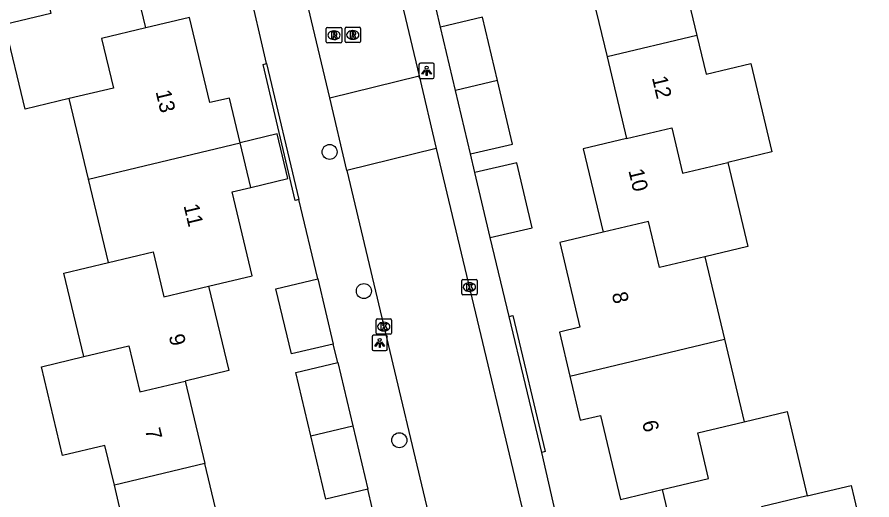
# Model space of a CAD drawing. Extents: x 158038 to 159242, y 380133 to 381214.
# Drawn here: x 158907 to 158962.6, y 380506.3 to 380537.7 of the extents above; entities that cross this region are included whole.
import ezdxf

# ---------------------------------------------------------------- set-up
doc = ezdxf.new("R2010")
doc.units = 0
for name, color, linetype in [('IMGEO_Boom', 7, 'Continuous'), ('IMGEO_Kolk', 7, 'Continuous'), ('IMGEO_Lichtpunt', 7, 'Continuous'), ('IMGEO_Muur', 7, 'Continuous'), ('IMGEO_Pand', 7, 'Continuous'), ('IMGEO_Pand_nummerreeks', 7, 'Continuous'), ('IMGEO_Rijbaan_lokaal_open', 7, 'Continuous'), ('IMGEO_Rioolput', 7, 'Continuous'), ('IMGEO_Voetpad_open', 7, 'Continuous')]:
    doc.layers.add(name, color=color, linetype=linetype)

msp = doc.modelspace()

# ---------------------------------------------------------------- linework, layer by layer
at = {"layer": 'IMGEO_Boom'}
for centre in [(158927.327, 380528.904), (158929.556, 380519.852), (158931.862, 380510.146)]:
    msp.add_circle(centre, 0.489, dxfattribs=at)
at = {"layer": 'IMGEO_Kolk'}
for p, q in [((158936.001, 380520.611), (158936.853, 380520.611)), ((158935.926, 380519.685), (158935.926, 380520.537)), ((158936.414, 380520.391), (158936.439, 380520.391)), ((158936.927, 380520.537), (158936.927, 380519.685)), ((158936.853, 380519.611), (158936.001, 380519.611)), ((158936.437, 380519.831), (158936.412, 380519.831)), ((158930.351, 380517.112), (158930.351, 380517.964)), ((158930.426, 380518.038), (158931.278, 380518.038)), ((158930.839, 380517.818), (158930.864, 380517.818)), ((158931.352, 380517.964), (158931.352, 380517.112)), ((158930.862, 380517.258), (158930.837, 380517.258)), ((158931.278, 380517.038), (158930.426, 380517.038))]:
    msp.add_line(p, q, dxfattribs=at)
for points in [[(158936.001, 380520.611), (158936.853, 380520.611)], [(158935.926, 380519.685), (158935.926, 380520.537)], [(158936.247, 380520.311), (158936.37, 380520.311), (158936.37, 380520.16), (158936.5, 380520.311), (158936.664, 380520.311), (158936.518, 380520.16), (158936.671, 380519.911), (158936.519, 380519.911), (158936.434, 380520.075), (158936.37, 380520.008), (158936.37, 380519.911), (158936.247, 380519.911), (158936.247, 380520.311)], [(158936.927, 380520.537), (158936.927, 380519.685)], [(158936.853, 380519.611), (158936.001, 380519.611)], [(158930.351, 380517.112), (158930.351, 380517.964)], [(158930.426, 380518.038), (158931.278, 380518.038)], [(158931.352, 380517.964), (158931.352, 380517.112)], [(158930.672, 380517.738), (158930.795, 380517.738), (158930.795, 380517.587), (158930.925, 380517.738), (158931.089, 380517.738), (158930.943, 380517.587), (158931.096, 380517.338), (158930.944, 380517.338), (158930.859, 380517.502), (158930.795, 380517.435), (158930.795, 380517.338), (158930.672, 380517.338), (158930.672, 380517.738)], [(158931.278, 380517.038), (158930.426, 380517.038)]]:
    msp.add_lwpolyline(points, dxfattribs=at)
for centre, start, end in [((158936.003, 380520.535), 91.552, 178.448), ((158936.003, 380520.535), 91.552, 178.448), ((158936.851, 380520.535), 1.552, 88.448), ((158936.851, 380520.535), 1.552, 88.448), ((158936.003, 380519.687), 181.552, 268.448), ((158936.003, 380519.687), 181.552, 268.448), ((158936.851, 380519.687), 271.552, 358.448), ((158936.851, 380519.687), 271.552, 358.448), ((158930.428, 380517.962), 91.552, 178.448), ((158930.428, 380517.962), 91.552, 178.448), ((158931.276, 380517.962), 1.552, 88.448), ((158931.276, 380517.962), 1.552, 88.448), ((158930.428, 380517.114), 181.552, 268.448), ((158930.428, 380517.114), 181.552, 268.448), ((158931.276, 380517.114), 271.552, 358.448), ((158931.276, 380517.114), 271.552, 358.448)]:
    msp.add_arc(centre, 0.0765, start, end, dxfattribs=at)
for centre, major_axis, ratio, start_param, end_param in [((158936.413, 380520.111), (-0.387, 0.002), 0.722429, 4.712389, 7.853982), ((158936.438, 380520.111), (-0.39, 0.002), 0.717154, 1.570796, 4.712389), ((158930.838, 380517.538), (-0.387, 0.002), 0.722429, 4.712389, 7.853982), ((158930.863, 380517.538), (-0.39, 0.002), 0.717154, 1.570796, 4.712389)]:
    msp.add_ellipse(centre, major_axis=major_axis, ratio=ratio, start_param=start_param, end_param=end_param, dxfattribs=at)
at = {"layer": 'IMGEO_Lichtpunt'}
for p, q in [((158933.142, 380534.586), (158933.142, 380533.779)), ((158933.142, 380534.586), (158933.142, 380533.779)), ((158934.044, 380534.681), (158933.236, 380534.681)), ((158934.044, 380534.681), (158933.236, 380534.681)), ((158934.138, 380533.779), (158934.138, 380534.586)), ((158934.138, 380533.779), (158934.138, 380534.586)), ((158933.236, 380533.685), (158934.044, 380533.685)), ((158933.236, 380533.685), (158934.044, 380533.685)), ((158930.087, 380516.878), (158930.087, 380516.071)), ((158930.087, 380516.878), (158930.087, 380516.071)), ((158930.989, 380516.973), (158930.181, 380516.973)), ((158930.989, 380516.973), (158930.181, 380516.973)), ((158931.083, 380516.071), (158931.083, 380516.878)), ((158931.083, 380516.071), (158931.083, 380516.878)), ((158930.181, 380515.977), (158930.989, 380515.977)), ((158930.181, 380515.977), (158930.989, 380515.977))]:
    msp.add_line(p, q, dxfattribs=at)
for points in [[(158933.516, 380534.25), (158933.555, 380534.222), (158933.367, 380533.96), (158933.329, 380533.987), (158933.516, 380534.25)], [(158933.618, 380534.202), (158933.665, 380534.202), (158933.665, 380533.88), (158933.618, 380533.88), (158933.618, 380534.202)], [(158933.728, 380534.222), (158933.766, 380534.249), (158933.953, 380533.987), (158933.914, 380533.959), (158933.728, 380534.222)], [(158930.461, 380516.542), (158930.5, 380516.514), (158930.312, 380516.252), (158930.274, 380516.279), (158930.461, 380516.542)], [(158930.563, 380516.494), (158930.61, 380516.494), (158930.61, 380516.172), (158930.563, 380516.172), (158930.563, 380516.494)], [(158930.673, 380516.514), (158930.711, 380516.541), (158930.898, 380516.279), (158930.859, 380516.251), (158930.673, 380516.514)]]:
    msp.add_lwpolyline(points, dxfattribs=at)
for centre in [(158933.641, 380534.384), (158930.586, 380516.676)]:
    msp.add_circle(centre, 0.0994, dxfattribs=at)
for centre, start, end in [((158933.236, 380534.586), 90, 180), ((158933.236, 380534.586), 90, 180), ((158934.044, 380534.586), 0, 90), ((158934.044, 380534.586), 0, 90), ((158933.236, 380533.779), 180, 270), ((158933.236, 380533.779), 180, 270), ((158934.044, 380533.779), 270, 0), ((158934.044, 380533.779), 270, 360), ((158930.181, 380516.878), 90, 180), ((158930.181, 380516.878), 90, 180), ((158930.989, 380516.878), 0, 90), ((158930.989, 380516.878), 0, 90), ((158930.181, 380516.071), 180, 270), ((158930.181, 380516.071), 180, 270), ((158930.989, 380516.071), 270, 0), ((158930.989, 380516.071), 270, 360)]:
    msp.add_arc(centre, 0.0946, start, end, dxfattribs=at)
at = {"layer": 'IMGEO_Muur'}
for points in [[(158925.319, 380525.8), (158925.085, 380525.745), (158922.996, 380534.593), (158923.23, 380534.648)], [(158923.23, 380534.648), (158925.319, 380525.8)], [(158939.008, 380518.196), (158939.241, 380518.252), (158941.36, 380509.413), (158941.127, 380509.357)], [(158941.127, 380509.357), (158939.008, 380518.196)]]:
    msp.add_lwpolyline(points, dxfattribs=at)
at = {"layer": 'IMGEO_Pand'}
for points in [[(158949.273, 380544.901), (158952.103, 380545.574), (158953.26, 380540.71), (158953.452, 380539.903), (158950.57, 380539.217), (158951.22, 380536.483)], [(158915.374, 380536.973), (158914.059, 380542.479), (158911.392, 380541.842)], [(158911.392, 380541.842), (158908.413, 380541.13), (158909.185, 380537.902), (158906.209, 380537.191)], [(158944.115, 380540.392), (158945.377, 380535.085)], [(158921.509, 380529.501), (158920.814, 380532.412), (158919.544, 380532.109), (158918.22, 380537.653), (158915.374, 380536.973)], [(158938.245, 380533.546), (158937.27, 380537.673), (158934.545, 380537.029)], [(158910.39, 380532.372), (158907.524, 380531.687), (158906.209, 380537.191)], [(158915.374, 380536.973), (158912.497, 380536.285), (158913.267, 380533.06), (158910.39, 380532.372)], [(158935.52, 380532.902), (158934.545, 380537.029)], [(158951.22, 380536.483), (158945.377, 380535.085)], [(158951.22, 380536.483), (158951.82, 380533.962), (158954.734, 380534.655), (158956.101, 380528.908), (158953.231, 380528.226)], [(158945.377, 380535.085), (158946.639, 380529.78)], [(158938.245, 380533.546), (158935.52, 380532.902)], [(158936.496, 380528.775), (158939.221, 380529.419), (158938.245, 380533.546)], [(158936.496, 380528.775), (158935.52, 380532.902)], [(158911.643, 380527.123), (158910.39, 380532.372)], [(158922.203, 380526.593), (158924.607, 380527.167), (158923.912, 380530.08), (158921.509, 380529.501)], [(158946.639, 380529.78), (158949.584, 380530.48), (158950.286, 380527.526), (158953.231, 380528.226)], [(158911.643, 380527.123), (158921.509, 380529.501)], [(158922.203, 380526.593), (158921.509, 380529.501)], [(158946.639, 380529.78), (158943.831, 380529.112), (158945.122, 380523.686)], [(158937.769, 380523.333), (158940.495, 380523.975), (158939.5, 380528.199), (158936.774, 380527.557)], [(158953.231, 380528.226), (158954.535, 380522.742), (158951.739, 380522.077)], [(158937.769, 380523.333), (158936.774, 380527.557)], [(158912.936, 380521.709), (158911.643, 380527.123)], [(158919.452, 380520.176), (158922.282, 380520.851), (158920.98, 380526.301), (158922.203, 380526.593)], [(158951.739, 380522.077), (158948.789, 380521.375), (158948.073, 380524.387), (158945.122, 380523.686)], [(158945.122, 380523.686), (158942.301, 380523.016), (158943.614, 380517.497), (158942.278, 380517.179), (158942.958, 380514.318)], [(158912.936, 380521.709), (158915.845, 380522.404), (158916.542, 380519.482), (158919.452, 380520.176)], [(158911.328, 380515.585), (158910.031, 380521.015), (158912.936, 380521.709)], [(158951.739, 380522.077), (158953.012, 380516.724)], [(158927.567, 380516.405), (158924.842, 380515.759), (158923.838, 380519.996), (158926.563, 380520.642)], [(158926.563, 380520.642), (158927.567, 380516.405)], [(158919.452, 380520.176), (158920.766, 380514.675), (158917.928, 380513.997)], [(158942.958, 380514.318), (158953.012, 380516.724)], [(158953.012, 380516.724), (158954.291, 380511.347)], [(158911.328, 380515.585), (158914.27, 380516.288), (158914.986, 380513.294), (158917.928, 380513.997)], [(158913.323, 380507.221), (158912.704, 380509.813), (158909.956, 380509.157), (158908.578, 380514.928), (158911.328, 380515.585)], [(158926.108, 380510.431), (158925.132, 380514.551), (158927.856, 380515.197)], [(158927.856, 380515.197), (158928.832, 380511.077)], [(158917.928, 380513.997), (158919.207, 380508.64)], [(158942.958, 380514.318), (158943.639, 380511.456), (158944.942, 380511.766), (158946.243, 380506.296), (158948.969, 380506.945)], [(158954.291, 380511.347), (158957.085, 380512.011), (158958.39, 380506.523)], [(158948.969, 380506.945), (158951.983, 380507.663), (158951.277, 380510.631), (158954.291, 380511.347)], [(158926.108, 380510.431), (158928.832, 380511.077)], [(158928.832, 380511.077), (158929.809, 380506.957)], [(158929.809, 380506.957), (158927.084, 380506.312), (158926.108, 380510.431)], [(158919.207, 380508.64), (158913.323, 380507.221)], [(158920.486, 380503.286), (158919.207, 380508.64)], [(158912.531, 380498.198), (158912.115, 380500), (158911.382, 380503.065), (158911.175, 380503.94), (158913.949, 380504.602), (158913.323, 380507.221)], [(158958.39, 380506.523), (158961.256, 380507.204), (158961.451, 380506.382), (158962.608, 380501.517), (158959.709, 380500.828), (158960.344, 380498.141)], [(158948.969, 380506.945), (158950.271, 380501.469), (158952.981, 380502.114)], [(158958.39, 380506.523), (158955.419, 380505.817), (158956.122, 380502.861), (158952.981, 380502.114)]]:
    msp.add_lwpolyline(points, dxfattribs=at)
at = {"layer": 'IMGEO_Rijbaan_lokaal_open'}
for points in [[(158928.109, 380555.067), (158933.156, 380533.858)], [(158927.337, 380532.423), (158922.291, 380553.668)], [(158927.337, 380532.423), (158933.156, 380533.858)], [(158933.156, 380533.858), (158934.264, 380529.122)], [(158928.452, 380527.7), (158927.337, 380532.423)], [(158934.264, 380529.122), (158928.452, 380527.7)], [(158934.264, 380529.122), (158941.908, 380497.067)], [(158928.452, 380527.7), (158936.101, 380495.467)]]:
    msp.add_lwpolyline(points, dxfattribs=at)
at = {"layer": 'IMGEO_Rioolput'}
for p, q in [((158927.113, 380536.073), (158927.113, 380536.925)), ((158927.188, 380536.999), (158928.04, 380536.999)), ((158927.601, 380536.779), (158927.626, 380536.779)), ((158928.114, 380536.925), (158928.114, 380536.073)), ((158928.334, 380536.089), (158928.334, 380536.941)), ((158928.409, 380537.015), (158929.261, 380537.015)), ((158928.822, 380536.795), (158928.847, 380536.795)), ((158929.335, 380536.941), (158929.335, 380536.089)), ((158927.624, 380536.219), (158927.599, 380536.219)), ((158928.845, 380536.235), (158928.82, 380536.235)), ((158928.04, 380535.999), (158927.188, 380535.999)), ((158929.261, 380536.015), (158928.409, 380536.015))]:
    msp.add_line(p, q, dxfattribs=at)
for points in [[(158927.113, 380536.073), (158927.113, 380536.925)], [(158927.188, 380536.999), (158928.04, 380536.999)], [(158927.702, 380536.697), (158927.45, 380536.699), (158927.45, 380536.299)], [(158928.114, 380536.925), (158928.114, 380536.073)], [(158928.334, 380536.089), (158928.334, 380536.941)], [(158928.409, 380537.015), (158929.261, 380537.015)], [(158928.923, 380536.713), (158928.671, 380536.715), (158928.671, 380536.315)], [(158929.335, 380536.941), (158929.335, 380536.089)], [(158927.45, 380536.299), (158927.574, 380536.299), (158927.574, 380536.461), (158927.585, 380536.461)], [(158927.628, 380536.618), (158927.574, 380536.618), (158927.574, 380536.537)], [(158927.574, 380536.537), (158927.626, 380536.537)], [(158927.632, 380536.432), (158927.703, 380536.299), (158927.843, 380536.299), (158927.778, 380536.425)], [(158928.671, 380536.315), (158928.795, 380536.315), (158928.795, 380536.477), (158928.806, 380536.477)], [(158928.849, 380536.634), (158928.795, 380536.634), (158928.795, 380536.553)], [(158928.795, 380536.553), (158928.847, 380536.553)], [(158928.853, 380536.448), (158928.924, 380536.315), (158929.064, 380536.315), (158928.999, 380536.441)], [(158928.04, 380535.999), (158927.188, 380535.999)], [(158929.261, 380536.015), (158928.409, 380536.015)]]:
    msp.add_lwpolyline(points, dxfattribs=at)
for centre, radius, start, end in [((158927.19, 380536.923), 0.0765, 91.552, 178.448), ((158927.19, 380536.923), 0.0765, 91.552, 178.448), ((158927.701, 380536.587), 0.109, 350.3612, 89.416), ((158928.038, 380536.923), 0.0765, 1.552, 88.448), ((158928.038, 380536.923), 0.0765, 1.552, 88.448), ((158928.411, 380536.939), 0.0765, 91.552, 178.448), ((158928.411, 380536.939), 0.0765, 91.552, 178.448), ((158928.922, 380536.603), 0.109, 350.3612, 89.416), ((158929.259, 380536.939), 0.0765, 1.552, 88.448), ((158929.259, 380536.939), 0.0765, 1.552, 88.448), ((158927.584, 380536.408), 0.0533, 26.0293, 88.6989), ((158927.61, 380536.726), 0.19, 274.7715, 282.9687), ((158927.634, 380536.522), 0.0964, 77.0061, 93.1865), ((158927.648, 380536.579), 0.0378, 276.6634, 79.6772), ((158927.699, 380536.587), 0.112, 277.5842, 350.9817), ((158927.683, 380536.372), 0.108, 29.5134, 73.7905), ((158928.805, 380536.424), 0.0533, 26.0293, 88.6989), ((158928.831, 380536.742), 0.19, 274.7715, 282.9687), ((158928.855, 380536.538), 0.0964, 77.0061, 93.1865), ((158928.869, 380536.595), 0.0378, 276.6634, 79.6772), ((158928.92, 380536.603), 0.112, 277.5842, 350.9817), ((158928.904, 380536.388), 0.108, 29.5134, 73.7905), ((158927.19, 380536.075), 0.0765, 181.552, 268.448), ((158927.19, 380536.075), 0.0765, 181.552, 268.448), ((158928.038, 380536.075), 0.0765, 271.552, 358.448), ((158928.038, 380536.075), 0.0765, 271.552, 358.448), ((158928.411, 380536.091), 0.0765, 181.552, 268.448), ((158928.411, 380536.091), 0.0765, 181.552, 268.448), ((158929.259, 380536.091), 0.0765, 271.552, 358.448), ((158929.259, 380536.091), 0.0765, 271.552, 358.448)]:
    msp.add_arc(centre, radius, start, end, dxfattribs=at)
for centre, major_axis, ratio, start_param, end_param in [((158927.6, 380536.499), (-0.387, 0.002), 0.722429, 4.712389, 7.853982), ((158927.625, 380536.499), (-0.39, 0.002), 0.717154, 1.570796, 4.712389), ((158928.821, 380536.515), (-0.387, 0.002), 0.722429, 4.712389, 7.853982), ((158928.846, 380536.515), (-0.39, 0.002), 0.717154, 1.570796, 4.712389)]:
    msp.add_ellipse(centre, major_axis=major_axis, ratio=ratio, start_param=start_param, end_param=end_param, dxfattribs=at)
at = {"layer": 'IMGEO_Voetpad_open'}
for points in [[(158923.23, 380534.648), (158922.031, 380539.837)], [(158934.545, 380537.029), (158934.257, 380538.231)], [(158936.774, 380527.557), (158936.496, 380528.775)], [(158926.563, 380520.642), (158925.319, 380525.8)], [(158939.008, 380518.196), (158937.769, 380523.333)], [(158927.856, 380515.197), (158927.567, 380516.405)], [(158942.333, 380504.122), (158941.127, 380509.357)], [(158930.1, 380505.74), (158929.809, 380506.957)]]:
    msp.add_lwpolyline(points, dxfattribs=at)

# ---------------------------------------------------------------- texts
at = {"layer": 'IMGEO_Pand_nummerreeks'}
for s, rotation, p in [('12', 283.3813, (158948.289, 380533.734)), ('13', 283.4316, (158916.002, 380532.823)), ('10', 283.3835, (158946.759, 380527.694)), ('11', 283.4361, (158917.82, 380525.411)), ('8', 283.2661, (158945.677, 380519.678)), ('9', 283.4343, (158916.854, 380516.932)), ('6', 283.2661, (158947.647, 380511.322)), ('7', 283.4282, (158915.313, 380510.825))]:
    msp.add_text(s, height=1, rotation=rotation, dxfattribs=at).set_placement(p)

doc.saveas('drawing.dxf')
